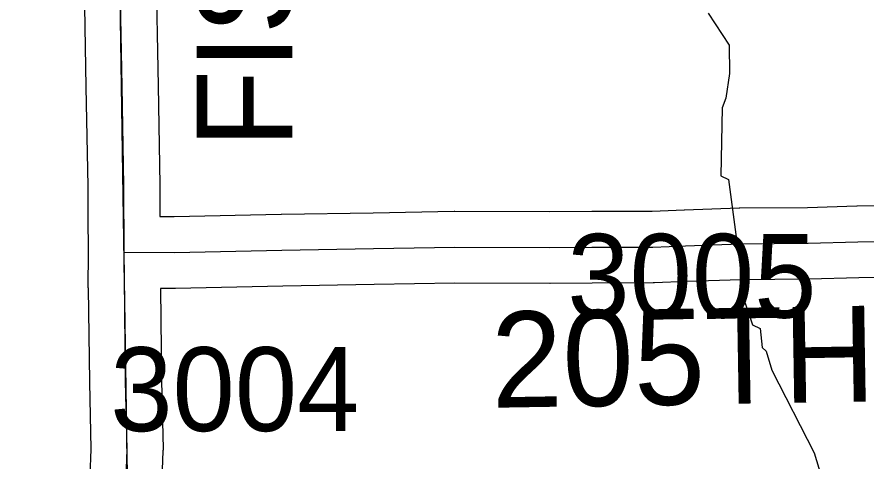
# Model space of a CAD drawing. Extents: x 23.6 to 68.7, y -63 to -29.
# Drawn here: x 38.585 to 39.295, y -44.357 to -43.985 of the extents above; entities that cross this region are included whole.
import ezdxf

# ---------------------------------------------------------------- set-up
doc = ezdxf.new("R2010")
doc.units = 0
for name, color, linetype in [('tdCoHydroRiver', 7, 'Continuous'), ('tdCoSecRdNmbr', 7, 'Continuous'), ('tdCoSecRdTxt', 7, 'Continuous'), ('tdCoSecRteBand', 7, 'Continuous'), ('tdCoSecRteCL', 7, 'Continuous'), ('tdCoSectLine', 7, 'Continuous'), ('tdCoSurfEarth', 7, 'Continuous'), ('tdCoSurfGravel', 7, 'Continuous'), ('tdCoTwpBndryShd', 7, 'Continuous')]:
    doc.layers.add(name, color=color, linetype=linetype)

msp = doc.modelspace()

# ---------------------------------------------------------------- linework, layer by layer
at = {"layer": 'tdCoHydroRiver'}
msp.add_lwpolyline([(39.16241, -43.98204), (39.18002, -44.00871), (39.18025, -44.03238), (39.17729, -44.05293), (39.1742, -44.06086), (39.17316, -44.11769), (39.1795, -44.12079), (39.1931, -44.22326), (39.19959, -44.24215), (39.20594, -44.24524), (39.20766, -44.26101), (39.21085, -44.26413), (39.21574, -44.27988), (39.25112, -44.34899), (39.25764, -44.37103)], dxfattribs=at)
at = {"layer": 'tdCoSecRteBand'}
for points in [[(38.64606, -44.36825), (38.64682, -44.34603), (38.64561, -44.28994), (38.64561, -44.2898), (38.6456, -44.28965), (38.64468, -44.21165), (38.64462, -44.21165), (38.64462, -44.21126), (38.64423, -44.21126), (38.64446, -44.18145), (38.6443, -44.15165), (38.64416, -44.12626), (38.64273, -44.04363), (38.64088, -43.94284)], [(38.70087, -43.94165), (38.70272, -44.04255), (38.70272, -44.04256), (38.70272, -44.04258), (38.70416, -44.1254), (38.70416, -44.12558), (38.70416, -44.12576), (38.7043, -44.15172), (38.71628, -44.15182)], [(38.71628, -44.15182), (38.8056, -44.14985), (38.80567, -44.14985), (38.80575, -44.14985), (38.88236, -44.14853), (38.88236, -44.14853), (38.88236, -44.14853), (38.9501, -44.14738), (38.95038, -44.14738), (38.95067, -44.14738), (39.03014, -44.14754), (39.06522, -44.14738), (39.06524, -44.14738), (39.06526, -44.14738), (39.11565, -44.14722), (39.14235, -44.14609), (39.1425, -44.14608), (39.14265, -44.14608), (39.18835, -44.1446), (39.18871, -44.14459), (39.18906, -44.14459), (39.24544, -44.1441), (39.28669, -44.14279), (39.28689, -44.14278), (39.28708, -44.14278), (39.33164, -44.14196)], [(39.33273, -44.20195), (39.28839, -44.20277), (39.24699, -44.20408), (39.24665, -44.20409), (39.2463, -44.20409), (39.18994, -44.20458), (39.14474, -44.20604), (39.11759, -44.20719), (39.11701, -44.20721), (39.11642, -44.20721), (39.06548, -44.20738), (39.03032, -44.20754), (39.03022, -44.20754), (39.03012, -44.20754), (38.95083, -44.20738), (38.88338, -44.20853), (38.80685, -44.20984), (38.71715, -44.21181), (38.71671, -44.21182), (38.71626, -44.21182), (38.70469, -44.21173), (38.7056, -44.28879), (38.70683, -44.34557), (38.70685, -44.34641), (38.70682, -44.34725), (38.70599, -44.37109)]]:
    msp.add_lwpolyline(points, dxfattribs=at)
at = {"layer": 'tdCoSecRteCL'}
for points in [[(38.67446, -44.18149), (38.67416, -44.12592), (38.67272, -44.0431), (38.67087, -43.9422), (38.66944, -43.88363), (38.66923, -43.83533), (38.6682, -43.77656), (38.66718, -43.72765), (38.66615, -43.64421), (38.66533, -43.57187), (38.6643, -43.48577), (38.66348, -43.44569), (38.66334, -43.43267)], [(38.67446, -44.18149), (38.7165, -44.18182), (38.80626, -44.17985), (38.88287, -44.17853), (38.95061, -44.17738), (39.03018, -44.17754), (39.06536, -44.17738), (39.11633, -44.17721), (39.14362, -44.17606), (39.18932, -44.17458), (39.24604, -44.17409), (39.28764, -44.17278), (39.33219, -44.17195), (39.42656, -44.17031), (39.50268, -44.16867), (39.56877, -44.16768), (39.60658, -44.16784), (39.64127, -44.16669), (39.64405, -44.16654), (39.64406, -44.16654)], [(38.58481, -44.59507), (38.59094, -44.58691), (38.59487, -44.58167), (38.59854, -44.5768), (38.61703, -44.54885), (38.63245, -44.52234), (38.64313, -44.50158), (38.65197, -44.48083), (38.6606, -44.45575), (38.66779, -44.42863), (38.67355, -44.39862), (38.67601, -44.37006), (38.67683, -44.34622), (38.6756, -44.28929), (38.67457, -44.20216), (38.67446, -44.18149)]]:
    msp.add_lwpolyline(points, dxfattribs=at)
at = {"layer": 'tdCoSectLine'}
msp.add_lwpolyline([(38.66621, -43.67708), (38.68154, -44.67704)], dxfattribs=at)
at = {"layer": 'tdCoSurfEarth'}
msp.add_lwpolyline([(38.67446, -44.18149), (38.7165, -44.18182), (38.80626, -44.17985), (38.88287, -44.17853), (38.95061, -44.17738), (39.03018, -44.17754), (39.06536, -44.17738), (39.11633, -44.17721), (39.14362, -44.17606), (39.18932, -44.17458), (39.24604, -44.17409), (39.28764, -44.17278), (39.33219, -44.17195), (39.42656, -44.17031), (39.50268, -44.16867), (39.56877, -44.16768), (39.60658, -44.16784), (39.64127, -44.16669), (39.64405, -44.16654)], dxfattribs=at)
at = {"layer": 'tdCoSurfGravel'}
msp.add_lwpolyline([(38.59094, -44.58691), (38.59487, -44.58167), (38.59854, -44.5768), (38.61703, -44.54885), (38.63245, -44.52234), (38.64313, -44.50158), (38.65197, -44.48083), (38.6606, -44.45575), (38.66779, -44.42863), (38.67355, -44.39862), (38.67601, -44.37006), (38.67683, -44.34622), (38.6756, -44.28929), (38.67457, -44.20216), (38.67446, -44.18149), (38.67416, -44.12592), (38.67272, -44.0431), (38.67087, -43.9422)], dxfattribs=at)
at = {"layer": 'tdCoTwpBndryShd'}
msp.add_lwpolyline([(38.62899, -40.68488), (38.63114, -41.6817), (38.66167, -42.68257), (38.66621, -43.67708), (38.68154, -44.67704), (38.69483, -45.68023), (38.71108, -46.64677), (38.7223, -47.6479), (38.73308, -48.65024), (38.76344, -49.65246), (38.77268, -50.65042), (38.78157, -51.65696), (38.78581, -52.6972), (38.80678, -53.6871), (38.81193, -54.68846), (38.82757, -55.69116), (38.83738, -56.6904), (38.86073, -57.68813)], dxfattribs=at)

# ---------------------------------------------------------------- texts
at = {"layer": 'tdCoSecRdNmbr'}
for s, rotation, p in [('3005', 0.03063, (39.04476, -44.23629)), ('3004', 0.03032, (38.66277, -44.33088))]:
    msp.add_text(s, height=0.07, rotation=rotation, dxfattribs=at).set_placement(p)
at = {"layer": 'tdCoSecRdTxt'}
for s, rotation, p in [('FISHER AVE', 90, (38.81501, -44.09468)), ('205TH ST', 0.95282, (38.98182, -44.31139))]:
    msp.add_text(s, height=0.08, rotation=rotation, dxfattribs=at).set_placement(p)

doc.saveas('drawing.dxf')
